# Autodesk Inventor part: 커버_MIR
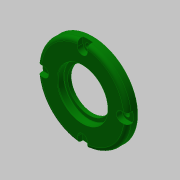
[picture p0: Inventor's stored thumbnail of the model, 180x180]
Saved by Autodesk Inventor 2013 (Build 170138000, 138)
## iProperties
Created: 2019-05
Part Number: 커버_MIR
Material: 알루미늄 6061
Document SubType Name: Modeling
Designer: user
Density: 2.71 g/cm^3
Author: mduedu
d0: 72.000 mm
d2: 52.000 mm
d3: 12.000 mm
d4: 4.000 mm
d6: 62.000 mm
d7: 8.000 mm
d8: 4.400 mm
d9: 0.00 deg
d10: 4.000 ul
d11: 360.00 deg
d13: 3.000 mm
d14: 40.000 mm
d16: 5.200 mm
d17: 46.000 mm
d18: 4.000 mm
d19: 34.000 mm
d21: 0.500 mm
d23: 30.00 deg
d24: 0.200 mm
d25: 3.000 mm
d26: 1.000 mm
d29: 62.000 mm
d30: 4.000 ul
d34: 4.500 mm
d32: 360.00 deg
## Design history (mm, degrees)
derived "커버.ipt"
  sketch "스케치1"
    geometry: L1 (0, 0)-(-36, 0) reference; L2 (-36, 0)-(-36, -8) reference; L3 (-36, -8)-(0, -8) reference; L4 (0, -8)-(0, 0) reference; L5 (0, -8)-(-26, -8) reference; L6 (-26, -8)-(-26, -12) reference; L7 (-26, -12)-(0, -12) reference; L8 (0, -12)-(0, -8) reference
  sketch "스케치2"
    geometry: L1 (4, 31)-(4, 35.777) reference; L2 (-4, 31)-(-4, 35.777) reference; A1 r 4 centre (0, 31) between (4, 31) and (-4, 31) reference; A2 r 36 centre (0, 0) between (4, 35.777) and (-4, 35.777) reference; A3 r 36 centre (0, 0) between (4, 35.777) and (-4, 35.777) reference; 2 further points
    constraints: 1 vertical alignment
  sketch "스케치3"
    geometry: L1 (-36, -4.4)-(-36, -8) reference; L2 (-36, -8)-(-26, -8) reference; L3 (-26, -8)-(-26, -12) reference; L4 (-26, -12)-(26, -12) reference; L5 (26, -12)-(26, -8) reference; L6 (26, -8)-(36, -8) reference; L7 (36, -8)-(36, -4.4) reference; L8 (36, -4.4)-(27, -4.4) reference; L9 (27, -4.4)-(27, 0) reference; L10 (27, 0)-(-27, 0) reference; L11 (-27, 0)-(-27, -4.4) reference; L12 (-27, -4.4)-(-36, -4.4) reference; L13 (0, 0)-(-20, 0) reference; L14 (-20, 0)-(-20, -5.2) reference; L15 (-20, -5.2)-(0, -5.2) reference; L16 (0, -5.2)-(0, 0) reference; L17 (0, -5.2)-(-17, -5.2) reference; L18 (-17, -5.2)-(-17, -8) reference; L19 (-17, -8)-(0, -8) reference; L20 (0, -8)-(0, -5.2) reference; L21 (0, -8)-(-23, -8) reference; L22 (-23, -8)-(-23, -12) reference; L23 (-23, -12)-(0, -12) reference; L24 (0, -12)-(0, -8) reference
  sketch "스케치4"
    geometry: 6 further points
    constraints: 1 vertical alignment, 1 other
  sketch "스케치5"
    geometry: 4 further points
feature "솔리드1::커버.ipt"
tag "피쳐 태그1"
node "솔리드1"
other parameters: "d0" = 10, "d0_1" = 72, "d2" = 52, "d3" = 12, "d4" = 4, "d6" = 62, "d7" = 8, "d8" = 4.4, "d9" = 0 deg, "d10" = 4, "d11" = 360 deg, "d13" = 3, "d14" = 40, "d16" = 5.2, "d17" = 46, "d18" = 4, "d19" = 34, "d21" = 0.5, "d23" = 30 deg, "d24" = 0.2, "d25" = 3, "d26" = 1, "d29" = 62, "d30" = 4, "d34" = 4.5, "d32" = 360 deg
